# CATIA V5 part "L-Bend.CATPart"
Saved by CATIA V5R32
Part number: L-Bend
Bounding box of the stored display mesh (mm): x -50 to 50, y -130 to 15, z -50 to 100
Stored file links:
  D:\PROJECTS\Project 2022\CATIA V5 6R 2022\Resources\Part Files\c12_catia_v5_6r2022_prt\c12_catia_v5-6r2022 figr_12-39\L-Bend.CATPart
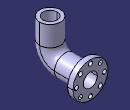
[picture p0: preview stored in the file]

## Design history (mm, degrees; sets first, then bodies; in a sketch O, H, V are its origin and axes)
Body1 (main body)
  Sketch1 on yz-plane, origin (0, 0, 0), H (0, 1, 0), V (0, 0, 1)
    line L1 (0, 0) -> (-57.4642, 0)
    point P1 (-100, 0)
    line L2 (-100, 42.5358) -> (-100, 100)
    point P2 (-100, 100)
    arc A1 centre (-57.4642, 42.5358) radius 42.5358 from (-100, 42.5358) to (-57.4642, 0) ccw
    distance P1 P2 = 100
    distance O P1 = 100
    radius A1 = 42.5358
    horizontal: L1 H
    vertical: L2 V
    coincidence: L2 P1, L1 P1
    tangency: A1 L2, A1 L1
  Sketch2 on zx-plane, origin (0, 0, 0), H (-1, 0, 0), V (0, 0, 1)
    circle A1 centre (0, 0) radius 30
    point P1 (0, -30)
    radius A1 = 30
    coincidence: A1 P1, P1 V
  Rib1: profile Sketch2, centre curve Sketch1
  Shell1: ExtOffset 0, Face (face of Rib1; face of Rib1), IntOffset 10
  Sketch3 on face of Rib1, origin (0, 0, 0), H (-1, 0, 0), V (0, 0, 1)
    circle A1 centre (0, 0) radius 50
    point P1 (0, -50)
    projected circle E1 centre (0, 0) radius 20 from edge [face of Shell1 | face of Rib1]
    radius A1 = 50
    coincidence: A1 P1, P1 V
  Pad1: profile Sketch3, direction (0, 1, 0), length 15
  Sketch4 on face of Pad1, origin (0, 15, 0), H (-1, 0, 0), V (0, 0, 1)
    circle A1 centre (0, -40) radius 6
    point P1 (0, -40)
    radius A1 = 6
    distance H P1 = 40
    coincidence: P1 V
  Pocket1: profile Sketch4, direction (0, -1, 0), length 15
  CircPattern1: of Pocket1, instances 8, angular step 45, axis from face of Pad1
